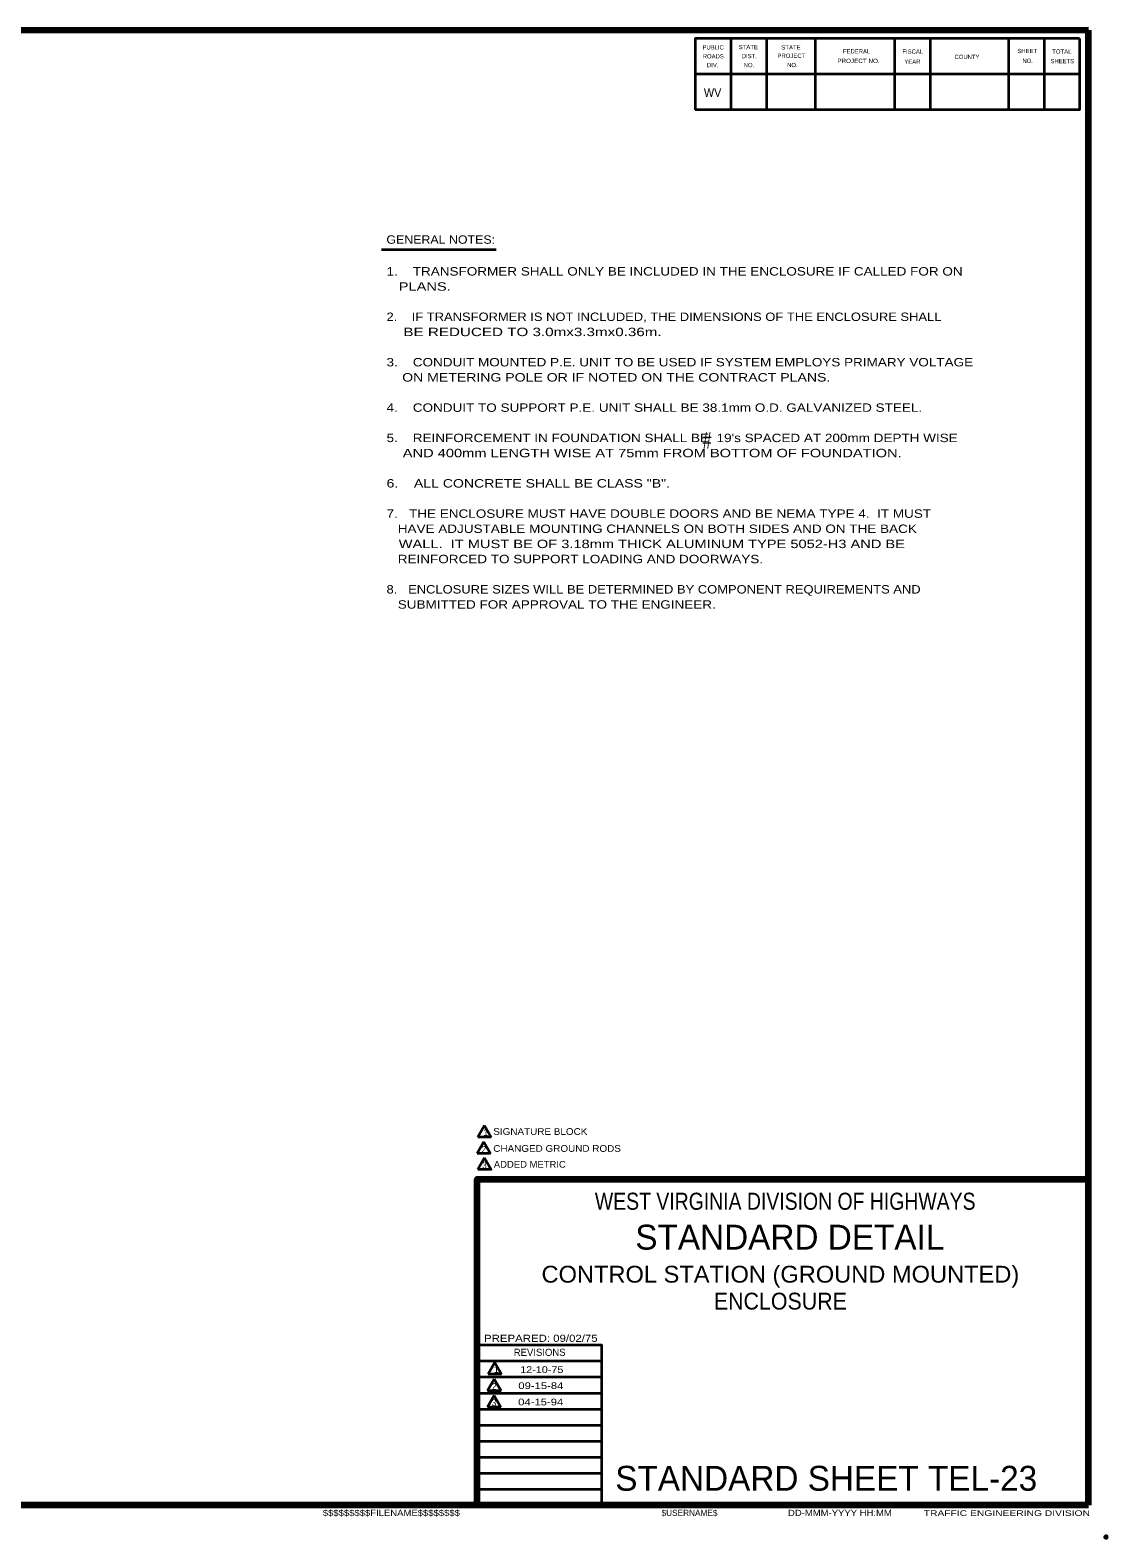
# Model space of a CAD drawing. Extents: x -30 to 826, y -11 to 533.
# Drawn here: x 442 to 826, y -11 to 527 of the extents above; entities that cross this region are included whole.
import ezdxf
from ezdxf.enums import TextEntityAlignment as Align

# ---------------------------------------------------------------- set-up
doc = ezdxf.new("R2010")
doc.units = 0
doc.header["$LTSCALE"] = 1.2
doc.header["$PDMODE"] = 32
doc.header["$PDSIZE"] = 0.6
doc.layers.add('1', color=7, linetype='Continuous', lineweight=53)
doc.layers.add('61', color=7, linetype='Continuous', lineweight=35)

msp = doc.modelspace()

# ---------------------------------------------------------------- linework, layer by layer
at = {"layer": '1', "lineweight": 158}
for q in [(819.196, 527.044), (819.196, 117.244), (27.596, 0.944)]:
    msp.add_line((819.196, 0.944), q, dxfattribs=at)
at = {"layer": '1', "lineweight": 13}
msp.add_line((819.196, 0.944), (819.196, 527.044), dxfattribs=at)
at = {"layer": '1', "lineweight": 35}
for p, q in [((567.168, 448.852), (608.049, 448.852)), ((603.828, 136.359), (601.428, 132.202)), ((603.828, 136.359), (606.228, 132.202)), ((603.629, 130.588), (601.229, 126.431)), ((606.228, 132.202), (601.428, 132.202)), ((603.629, 130.588), (606.029, 126.431)), ((606.029, 126.431), (601.229, 126.431)), ((603.838, 124.926), (601.438, 120.769)), ((645.696, 52.344), (601.196, 52.344)), ((607.541, 51.822), (605.141, 47.665)), ((607.541, 51.822), (609.941, 47.665)), ((645.696, 46.644), (601.196, 46.644)), ((607.352, 45.97), (604.952, 41.813)), ((609.941, 47.665), (605.141, 47.665)), ((607.352, 45.97), (609.752, 41.813)), ((645.696, 40.844), (601.196, 40.844)), ((607.296, 40.154), (604.896, 35.998)), ((609.752, 41.813), (604.952, 41.813)), ((607.296, 40.154), (609.696, 35.998)), ((645.696, 35.144), (601.196, 35.144)), ((609.696, 35.998), (604.896, 35.998)), ((645.696, 29.444), (601.196, 29.444)), ((645.696, 23.744), (601.196, 23.744)), ((645.696, 18.044), (601.196, 18.044)), ((645.696, 12.344), (601.196, 12.344)), ((645.696, 6.644), (601.196, 6.644))]:
    msp.add_line(p, q, dxfattribs=at)
at = {"layer": '1', "lineweight": 158}
for points in [[(819.196, 527.044), (27.496, 526.944), (27.596, 0.944)], [(601.196, 0.944), (601.196, 117.244), (819.196, 117.244)]]:
    msp.add_lwpolyline(points, dxfattribs=at)
at = {"layer": '1', "lineweight": 35}
for points in [[(603.838, 124.926), (606.238, 120.769), (601.438, 120.769)], [(645.696, 0.944), (645.696, 58.044), (601.196, 58.044)]]:
    msp.add_lwpolyline(points, dxfattribs=at)
at = {"layer": '1'}
msp.add_point((825.496, -10.356), dxfattribs=at)
at = {"layer": '61'}
for p, q in [((691.696, 524.044), (691.696, 498.644)), ((704.396, 524.044), (704.396, 498.644)), ((721.796, 524.044), (721.796, 498.644)), ((750.096, 524.044), (750.096, 498.644)), ((762.796, 524.044), (762.796, 498.644)), ((790.696, 524.044), (790.696, 498.644)), ((803.396, 524.044), (803.396, 498.644)), ((816.096, 511.344), (678.996, 511.344))]:
    msp.add_line(p, q, dxfattribs=at)
at = {"layer": '61', "lineweight": 53}
for q in [(666.496, 0.944), (666.496, 0.944), (666.496, 0.944), (666.796, 0.944), (666.796, 0.944)]:
    msp.add_line((819.196, 0.944), q, dxfattribs=at)
at = {"layer": '61'}
for points in [[(816.096, 524.044), (678.996, 524.044), (678.996, 498.644)], [(816.096, 524.044), (816.096, 498.644), (678.996, 498.644)]]:
    msp.add_lwpolyline(points, dxfattribs=at)

# ---------------------------------------------------------------- texts
at = {"layer": '1'}
for s, height, width, p in [('WV', 3.048, 0.95, (682.096, 503.244)), ('1.    TRANSFORMER SHALL ONLY BE INCLUDED IN THE ENCLOSURE IF CALLED FOR ON', 3, 1.2, (568.925, 439.525)), ('   PLANS.', 3, 1.3, (568.925, 434.125)), ('2.    IF TRANSFORMER IS NOT INCLUDED, THE DIMENSIONS OF THE ENCLOSURE SHALL', 3, 1.15, (568.925, 423.325)), ('    BE REDUCED TO 3.0mx3.3mx0.36m.', 3, 1.35, (568.925, 417.925)), ('3.    CONDUIT MOUNTED P.E. UNIT TO BE USED IF SYSTEM EMPLOYS PRIMARY VOLTAGE', 3, 1.2, (568.925, 407.125)), ('    ON METERING POLE OR IF NOTED ON THE CONTRACT PLANS.', 3, 1.25, (568.925, 401.725)), ('4.    CONDUIT TO SUPPORT P.E. UNIT SHALL BE 38.1mm O.D. GALVANIZED STEEL.', 3, 1.2, (568.925, 390.925)), ("5.    REINFORCEMENT IN FOUNDATION SHALL BE  19's SPACED AT 200mm DEPTH WISE", 3, 1.2, (568.925, 380.125)), ('#', 6, 0.7, (681.679, 377.822)), ('    AND 400mm LENGTH WISE AT 75mm FROM BOTTOM OF FOUNDATION.', 3, 1.3, (568.925, 374.725)), ('6.    ALL CONCRETE SHALL BE CLASS "B".', 3, 1.25, (568.925, 363.925)), ('7.   THE ENCLOSURE MUST HAVE DOUBLE DOORS AND BE NEMA TYPE 4.  IT MUST', 3, 1.2, (568.925, 353.125)), ('   HAVE ADJUSTABLE MOUNTING CHANNELS ON BOTH SIDES AND ON THE BACK', 3, 1.2, (568.925, 347.725)), ('   WALL.  IT MUST BE OF 3.18mm THICK ALUMINUM TYPE 5052-H3 AND BE', 3, 1.3, (568.925, 342.325)), ('   REINFORCED TO SUPPORT LOADING AND DOORWAYS.', 3, 1.2, (568.925, 336.925)), ('8.   ENCLOSURE SIZES WILL BE DETERMINED BY COMPONENT REQUIREMENTS AND', 3, 1.15, (568.925, 326.125)), ('   SUBMITTED FOR APPROVAL TO THE ENGINEER.', 3, 1.2, (568.925, 320.725)), ('SIGNATURE BLOCK', 2.4, 1.1, (606.991, 133.051)), ('2', 2.4, 0.9, (602.826, 126.715)), ('2', 2.4, 0.9, (602.826, 126.715)), ('2', 2.4, 0.9, (602.826, 126.715)), ('CHANGED GROUND RODS', 2.4, 1.1, (606.991, 127.013)), ('ADDED METRIC', 2.4, 1.05, (607.201, 121.351)), ('3', 2.4, 0.9, (603.035, 121.053)), ('PREPARED: 09/02/75', 2.537, 1.2, (603.696, 59.244)), ('2', 2.4, 0.9, (606.524, 42.134)), ('3', 2.4, 0.9, (606.468, 36.319)), ('$$$$$$$$$FILENAME$$$$$$$$', 2.2, 1.15, (546.196, -2.856)), ('DD-MMM-YYYY HH:MM', 2.2, 1.15, (712.096, -2.856)), ('TRAFFIC ENGINEERING DIVISION', 2.031, 1.35, (760.496, -2.856))]:
    msp.add_text(s, height=height, dxfattribs=dict(at, width=width)).set_placement(p)
for s, height, width, p in [('GENERAL NOTES:', 3, 1.1, (588.25, 450.867)), ('WEST VIRGINIA DIVISION OF HIGHWAYS', 6.089, 0.85, (711.096, 106.344)), ('CONTROL STATION (GROUND MOUNTED)', 6, 1.05, (709.37, 80.367)), ('ENCLOSURE', 6, 0.95, (709.37, 70.767)), ('12-10-75', 2.4, 1.2, (624.287, 48.143)), ('09-15-84', 2.4, 1.25, (623.956, 42.401)), ('04-15-94', 2.4, 1.25, (623.909, 36.586))]:
    msp.add_text(s, height=height, dxfattribs=dict(at, width=width)).set_placement(p, align=Align.CENTER)
for s, height, p in [('1', 2.4, (603.421, 132.754)), ('REVISIONS', 2.537, (614.296, 54.244)), ('1', 2.4, (607.194, 48.175)), ('STANDARD SHEET TEL-23', 8.881, (650.496, 6.144)), ('$USERNAME$', 2.2, (666.996, -2.856))]:
    msp.add_text(s, height=height, dxfattribs=at).set_placement(p)
msp.add_text('STANDARD DETAIL', height=8.881, dxfattribs=at).set_placement((712.746, 92.144), align=Align.CENTER)
at = {"layer": '61'}
for s, height, rotation, p in [('PUBLIC', 1.525, 0.033, (681.596, 520.144)), ('ROADS', 1.525, 0.124, (681.696, 516.944)), ('DIST.', 1.525, 0.056, (695.596, 517.044)), ('FEDERAL', 1.523, 0.007, (731.696, 518.744)), ('FISCAL', 1.525, 359.942, (752.896, 518.644)), ('YEAR', 1.523, 0.105, (753.596, 515.044)), ('COUNTY', 1.523, 0.069, (771.496, 516.744)), ('SHEET', 1.525, 0.059, (793.896, 518.844)), ('SHEETS', 1.523, 359.959, (805.696, 515.244)), ('DIV.', 1.525, 359.932, (683.196, 513.844))]:
    msp.add_text(s, height=height, rotation=rotation, dxfattribs=at).set_placement(p)
for s, rotation, width, p in [('STATE', 0.059, 1.05, (694.496, 520.244)), ('STATE', 0.059, 1.05, (709.696, 520.144)), ('PROJECT', 359.908, 1.05, (708.296, 517.144)), ('PROJECT NO.', 359.922, 1.1, (729.696, 515.344)), ('NO.', 359.852, 0.9, (795.696, 515.344)), ('TOTAL', 359.926, 1.05, (806.296, 518.644)), ('NO.', 359.852, 0.9, (696.296, 513.844)), ('NO.', 0.225, 0.9, (711.796, 513.844))]:
    msp.add_text(s, height=1.525, rotation=rotation, dxfattribs=dict(at, width=width)).set_placement(p)

doc.saveas('drawing.dxf')
